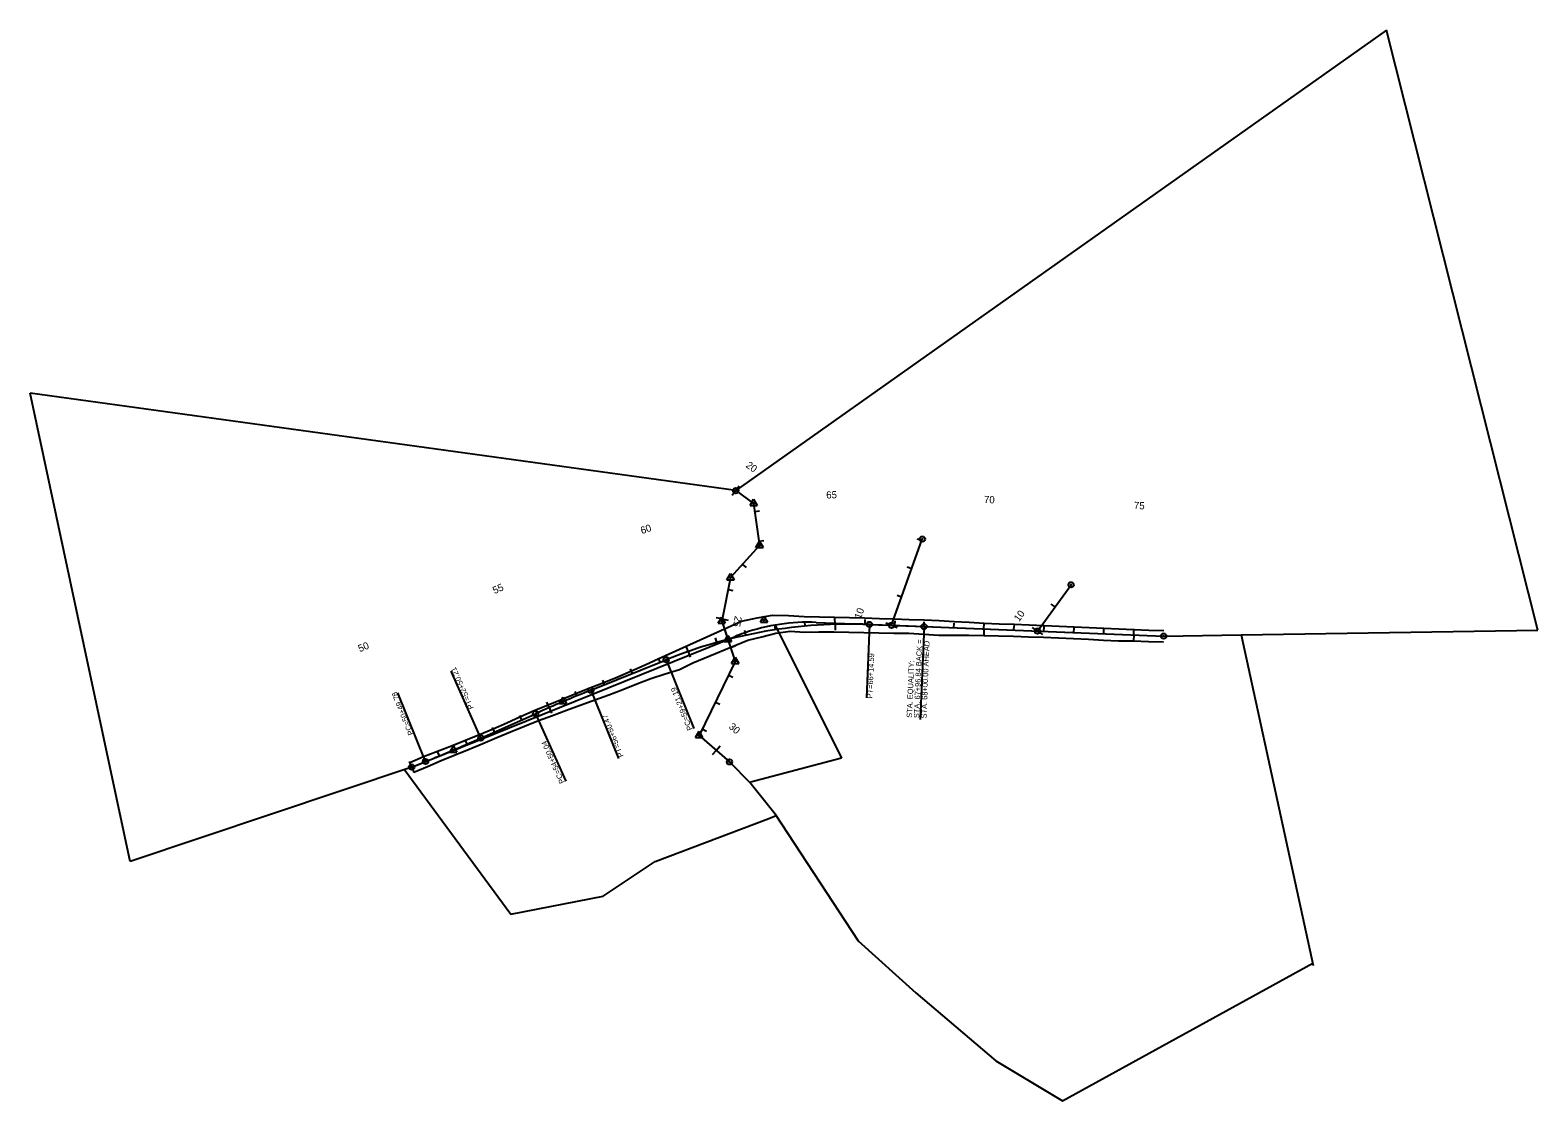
# Model space of a CAD drawing. Extents: x 1965498 to 1970527, y 1116335 to 1119906.
import ezdxf

# ---------------------------------------------------------------- set-up
doc = ezdxf.new("R2010")
doc.units = 0
for name, color, linetype in [('RD_EX_DV_Prop', 7, 'Continuous'), ('RD_EX_RW', 7, 'Continuous'), ('RD_HC_CL', 7, 'Continuous'), ('RD_HC_CL_Rel', 7, 'Continuous'), ('RD_HC_Data', 7, 'Continuous'), ('RD_HC_Data_Rel', 7, 'Continuous'), ('RD_HC_Data_Tic_Rel', 7, 'Continuous'), ('RD_HC_TX_Rel_Sta50', 7, 'Continuous'), ('RD_HC_TX_StaOther', 7, 'Continuous'), ('RD_Sketch2', 7, 'Continuous')]:
    doc.layers.add(name, color=color, linetype=linetype)

msp = doc.modelspace()

# ---------------------------------------------------------------- linework, layer by layer
at = {"layer": 'RD_EX_DV_Prop'}
for p, q in [((1970021.7, 1119906.4), (1967851.7, 1118370.2)), ((1970527.1, 1117904.7), (1970021.7, 1119906.4)), ((1965831.2, 1117132.9), (1965498.1, 1118695)), ((1967851.7, 1118370.2), (1965498.1, 1118695)), ((1967851.7, 1118370.2), (1967911.4, 1118327.7)), ((1967911.4, 1118327.7), (1967931.1, 1118187.5)), ((1967931.1, 1118187.5), (1967834, 1118080)), ((1967834, 1118080), (1967804.8, 1117934.9)), ((1967804.8, 1117934.9), (1967825.2, 1117874.1)), ((1967983.3, 1117921.8), (1968204.3, 1117478.1)), ((1968120.3, 1117930.9), (1968371.4, 1117921)), ((1968371.4, 1117921), (1969279, 1117884.9)), ((1969279, 1117884.9), (1969537.8, 1117889)), ((1969537.8, 1117889), (1970527.1, 1117904.7)), ((1969537.8, 1117889), (1969777.4, 1116786.4)), ((1967698.1, 1117822.7), (1967825.2, 1117874.1)), ((1967825.2, 1117874.1), (1967849.5, 1117883.9)), ((1967825.2, 1117874.1), (1967849.8, 1117800.6)), ((1966770.7, 1117448.1), (1967698.1, 1117822.7)), ((1967849.8, 1117800.6), (1967729.3, 1117553.7)), ((1967729.3, 1117553.7), (1967830.8, 1117465.4)), ((1966770.7, 1117448.1), (1965831.2, 1117132.9)), ((1966745.7, 1117440.8), (1967101.3, 1116957.5)), ((1967830.8, 1117465.4), (1967898.1, 1117396.8)), ((1968204.3, 1117478.1), (1967897.6, 1117396.5)), ((1967983, 1117291.4), (1967898.1, 1117396.8)), ((1967962.1, 1117277.1), (1967986.9, 1117286.5)), ((1967983, 1117291.4), (1968260.1, 1116868.2)), ((1967986.9, 1117286.5), (1967983, 1117291.4)), ((1967582.6, 1117133.3), (1967962.1, 1117277.1)), ((1967409.3, 1117017.8), (1967582.6, 1117133.3)), ((1967101.3, 1116957.5), (1967409.3, 1117017.8)), ((1968260.1, 1116868.2), (1968452.8, 1116695.3)), ((1968941.8, 1116334.8), (1969776.6, 1116794.1)), ((1968452.8, 1116695.3), (1968719.5, 1116468.1)), ((1968719.5, 1116468.1), (1968941.8, 1116334.8))]:
    msp.add_line(p, q, dxfattribs=at)
for start, end in [(109.2117, 111.9958), (87.7266, 109.2117)]:
    msp.add_arc((1968094.4, 1117277.5), 653.9, start, end, dxfattribs=at)
at = {"layer": 'RD_EX_RW'}
for points in [[(1967870.6, 1117935.4), (1967922.7, 1117945.6), (1967974.5, 1117955.3), (1968027.5, 1117953.6), (1968079.5, 1117951), (1968130.7, 1117949), (1968180.7, 1117948.4), (1968230.7, 1117947.1), (1968280.6, 1117945.5), (1968330.6, 1117944), (1968380.6, 1117942.5), (1968430.6, 1117940.9), (1968480.5, 1117939.1), (1968530.5, 1117937.2), (1968580.4, 1117934.2), (1968630.3, 1117931.2), (1968680.3, 1117928.2), (1968730.2, 1117926.4), (1968780.2, 1117924.7), (1968830.1, 1117922.4), (1968880.1, 1117920.9), (1968930, 1117917.9), (1968980, 1117915.8), (1969030, 1117913.7), (1969079.9, 1117911.5), (1969129.9, 1117909.2), (1969179.8, 1117906.8), (1969229.8, 1117904.9), (1969279.7, 1117903.2)], [(1966764.8, 1117463.1), (1966810.5, 1117483.1), (1966857.3, 1117500.8), (1966903.7, 1117519.3), (1966950.1, 1117538.2), (1966996.4, 1117557), (1967042.7, 1117575.8), (1967088.6, 1117595.7), (1967134, 1117616.8), (1967179.6, 1117637.3), (1967226.1, 1117655.7), (1967272.5, 1117674.3), (1967318.5, 1117694.1), (1967365.1, 1117712.2), (1967411.6, 1117730.5), (1967458.2, 1117748.8), (1967504.1, 1117768.7), (1967549.8, 1117788.8), (1967595.2, 1117810), (1967686.2, 1117851.8), (1967870.6, 1117935.4)], [(1967663.6, 1117774.2), (1967708.8, 1117795.8), (1967892.1, 1117872), (1967938.9, 1117882.9), (1967985.3, 1117894.6), (1968032.7, 1117901.4), (1968080.7, 1117898.1), (1968128.7, 1117899.3), (1968178.7, 1117899.4), (1968228.7, 1117898.2), (1968278.7, 1117896.8), (1968328.7, 1117895.5), (1968378.7, 1117895.2), (1968428.7, 1117894.5), (1968478.6, 1117891.5), (1968528.6, 1117888.4), (1968578.6, 1117888), (1968628.6, 1117887.7), (1968678.6, 1117887.4), (1968728.6, 1117886.1), (1968778.6, 1117884.7), (1968828.6, 1117882.9), (1968878.6, 1117881.2), (1968928.5, 1117879.4), (1968978.5, 1117877.6), (1969028.4, 1117874.5), (1969078.3, 1117871.2), (1969128.3, 1117869.8), (1969178.3, 1117868.8), (1969228.3, 1117867.4), (1969278.3, 1117865.8), (1969278.7, 1117865.8)], [(1966777.6, 1117431), (1966823.7, 1117450.6), (1966869.6, 1117470.3), (1966915.9, 1117489.2), (1966962.2, 1117508), (1967008.4, 1117527.3), (1967054.2, 1117547.3), (1967100.7, 1117565.7), (1967146.8, 1117585), (1967193.3, 1117603.6), (1967240.4, 1117620.4), (1967287.4, 1117637.6), (1967381.3, 1117672.1), (1967428.1, 1117689.7), (1967474.9, 1117707.3), (1967521.5, 1117725.4), (1967568.1, 1117743.6), (1967615.7, 1117759.4), (1967663.6, 1117774.2)]]:
    msp.add_lwpolyline(points, dxfattribs=at)
at = {"layer": 'RD_HC_CL'}
for p, q in [((1967851.7, 1118370.2), (1967911.4, 1118327.7)), ((1967911.4, 1118327.7), (1967931.1, 1118187.5)), ((1968371.4, 1117921), (1968474, 1118208.6)), ((1967931.1, 1118187.5), (1967834, 1118080)), ((1967834, 1118080), (1967804.8, 1117934.9)), ((1968858.2, 1117901.7), (1968970.1, 1118056.2)), ((1967804.8, 1117934.9), (1967849.8, 1117800.6)), ((1967849.8, 1117800.6), (1967729.3, 1117553.7)), ((1967729.3, 1117553.7), (1967830.8, 1117465.4))]:
    msp.add_line(p, q, dxfattribs=at)
at = {"layer": 'RD_HC_CL_Rel'}
for p, q in [((1968297.5, 1117923.9), (1968479.6, 1117916.7)), ((1968479.6, 1117916.7), (1969279, 1117884.9)), ((1967368.4, 1117704.6), (1967619.4, 1117806)), ((1967001.4, 1117545.1), (1967183.9, 1117626.3)), ((1966770.7, 1117448.1), (1966816.9, 1117466.8))]:
    msp.add_line(p, q, dxfattribs=at)
for centre, radius, start, end in [((1968232.6, 1116288.2), 1637, 87.7266, 111.9958), ((1969514.4, 1112392.1), 5729.6, 111.99584, 114.00015), ((1964670.9, 1122779.3), 5729.6, 291.9959, 294.00015)]:
    msp.add_arc(centre, radius, start, end, dxfattribs=at)
at = {"layer": 'RD_HC_Data'}
for p, q in [((1967851.7, 1118370.2), (1967840.1, 1118354)), ((1967851.7, 1118370.2), (1967863.4, 1118386.5)), ((1967899.5, 1118320.8), (1967911.4, 1118341.4)), ((1967911.4, 1118341.4), (1967923.3, 1118320.8)), ((1967899.5, 1118320.8), (1967923.3, 1118320.8)), ((1967915.1, 1118301.2), (1967930.9, 1118303.4)), ((1967919.1, 1118180.7), (1967931.1, 1118201.3)), ((1967929, 1118202.2), (1967944.8, 1118204.4)), ((1967931.1, 1118201.3), (1967943, 1118180.7)), ((1968472.1, 1118203.5), (1968457.1, 1118208.9)), ((1967919.1, 1118180.7), (1967943, 1118180.7)), ((1967822.1, 1118073.1), (1967834, 1118093.7)), ((1967834, 1118093.7), (1967845.9, 1118073.1)), ((1967874, 1118124.2), (1967885.9, 1118113.5)), ((1968438.5, 1118109.4), (1968423.5, 1118114.7)), ((1967822.1, 1118073.1), (1967845.9, 1118073.1)), ((1967826.1, 1118040.4), (1967841.7, 1118037.2)), ((1968404.9, 1118015.2), (1968389.9, 1118020.5)), ((1968916.8, 1117982.6), (1968903.9, 1117992)), ((1967806.3, 1117942.4), (1967786.7, 1117946.3)), ((1967792.9, 1117928), (1967804.8, 1117948.6)), ((1967804.8, 1117948.6), (1967816.7, 1117928)), ((1967806.3, 1117942.4), (1967825.9, 1117938.4)), ((1967792.9, 1117928), (1967816.7, 1117928)), ((1967813.4, 1117866.9), (1967825.3, 1117887.5)), ((1967825.3, 1117887.5), (1967837.2, 1117866.9)), ((1968371.4, 1117921), (1968352.5, 1117927.7)), ((1968371.4, 1117921), (1968390.2, 1117914.3)), ((1968858.2, 1117901.7), (1968842, 1117913.4)), ((1968858.2, 1117901.7), (1968874.4, 1117889.9)), ((1967813.4, 1117866.9), (1967837.2, 1117866.9)), ((1967834.2, 1117847.3), (1967849.3, 1117852.4)), ((1967837.9, 1117793.7), (1967849.8, 1117814.4)), ((1967837.9, 1117793.7), (1967861.7, 1117793.7)), ((1967849.8, 1117814.4), (1967861.7, 1117793.7)), ((1967827.6, 1117755), (1967841.9, 1117748)), ((1967783.7, 1117665.1), (1967798.1, 1117658.1)), ((1967717.4, 1117546.8), (1967729.3, 1117567.4)), ((1967717.4, 1117546.8), (1967741.2, 1117546.8)), ((1967729.3, 1117567.4), (1967741.2, 1117546.8)), ((1967739.8, 1117575.2), (1967754.2, 1117568.2)), ((1967786.6, 1117503.8), (1967773.5, 1117488.7)), ((1967786.6, 1117503.8), (1967799.8, 1117518.9))]:
    msp.add_line(p, q, dxfattribs=at)
for centre, radius in [((1967851.7, 1118370.2), 9), ((1967851.7, 1118370.2), 0.845), ((1967911.4, 1118327.7), 1.59), ((1967931.1, 1118187.5), 1.59), ((1968474, 1118208.6), 9), ((1968474, 1118208.6), 0.845), ((1967834, 1118080), 1.59), ((1968970.1, 1118056.2), 9), ((1968970.1, 1118056.2), 0.845), ((1967804.8, 1117934.9), 1.59), ((1968371.4, 1117921), 9), ((1968371.4, 1117921), 0.845), ((1968858.2, 1117901.7), 9), ((1968858.2, 1117901.7), 0.845), ((1967825.3, 1117873.7), 1.59), ((1967849.8, 1117800.6), 1.59), ((1967729.3, 1117553.7), 1.59), ((1967830.8, 1117465.4), 9), ((1967830.8, 1117465.4), 0.845)]:
    msp.add_circle(centre, radius, dxfattribs=at)
at = {"layer": 'RD_HC_Data_Rel'}
for p, q in [((1967933.9, 1117931), (1967945.8, 1117951.6)), ((1967945.8, 1117951.6), (1967957.7, 1117931)), ((1967933.9, 1117931), (1967957.7, 1117931)), ((1968297.5, 1117923.9), (1968287.8, 1117678.6)), ((1968479.6, 1117916.7), (1968467.3, 1117606.4)), ((1967619.4, 1117806), (1967712, 1117577)), ((1967001.4, 1117545.1), (1966902.3, 1117767.7)), ((1966816.9, 1117466.8), (1966724.5, 1117695.5)), ((1967368.4, 1117704.6), (1967460.4, 1117477)), ((1967263.6, 1117660.2), (1967275.5, 1117680.9)), ((1967263.6, 1117660.2), (1967287.4, 1117660.2)), ((1967275.5, 1117680.9), (1967287.4, 1117660.2)), ((1967183.9, 1117626.3), (1967284.4, 1117400.7)), ((1966897.9, 1117497.4), (1966909.8, 1117518.1)), ((1966897.9, 1117497.4), (1966921.7, 1117497.4)), ((1966909.8, 1117518.1), (1966921.7, 1117497.4))]:
    msp.add_line(p, q, dxfattribs=at)
for centre, radius in [((1967945.8, 1117937.9), 1.59), ((1968297.5, 1117923.9), 9), ((1968297.5, 1117923.9), 0.845), ((1968479.6, 1117916.7), 9), ((1968479.6, 1117916.7), 0.845), ((1969279, 1117884.9), 9), ((1969279, 1117884.9), 0.845), ((1967619.4, 1117806), 9), ((1967619.4, 1117806), 0.845), ((1967368.4, 1117704.6), 9), ((1967368.4, 1117704.6), 0.845), ((1967183.9, 1117626.3), 9), ((1967275.5, 1117667.1), 1.59), ((1967183.9, 1117626.3), 0.845), ((1967001.4, 1117545.1), 9), ((1967001.4, 1117545.1), 0.845), ((1966909.8, 1117504.3), 1.59), ((1966770.7, 1117448.1), 9), ((1966770.7, 1117448.1), 0.845), ((1966816.9, 1117466.8), 9), ((1966816.9, 1117466.8), 0.845)]:
    msp.add_circle(centre, radius, dxfattribs=at)
at = {"layer": 'RD_HC_Data_Tic_Rel'}
for p, q in [((1968182.9, 1117924.4), (1968182.3, 1117944.4)), ((1968282.9, 1117924.4), (1968283.4, 1117940.4)), ((1967885.6, 1117888), (1967882.2, 1117903.6)), ((1967983.9, 1117906.2), (1967981.5, 1117922)), ((1968083.1, 1117918.4), (1968081.7, 1117934.3)), ((1968182.9, 1117924.4), (1968183.5, 1117904.5)), ((1968382.8, 1117920.5), (1968383.5, 1117936.5)), ((1968479.6, 1117916.7), (1968480.3, 1117932.7)), ((1968579.6, 1117912.7), (1968580.2, 1117928.7)), ((1968679.5, 1117908.7), (1968678.7, 1117888.8)), ((1968679.5, 1117908.7), (1968680.3, 1117928.7)), ((1968779.4, 1117904.8), (1968780, 1117920.8)), ((1968879.3, 1117900.8), (1968880, 1117916.8)), ((1968979.3, 1117896.8), (1968979.9, 1117912.8)), ((1969079.2, 1117892.9), (1969079.8, 1117908.9)), ((1969179.1, 1117888.9), (1969178.3, 1117868.9)), ((1969179.1, 1117888.9), (1969179.9, 1117908.9)), ((1967693.2, 1117833.8), (1967686.6, 1117852.7)), ((1967788.6, 1117863.8), (1967784.2, 1117879.2)), ((1967599.8, 1117798.1), (1967593.8, 1117812.9)), ((1967693.2, 1117833.8), (1967699.8, 1117814.9)), ((1967414.4, 1117723.2), (1967408.4, 1117738)), ((1967507.1, 1117760.7), (1967501.1, 1117775.5)), ((1967321.7, 1117685.5), (1967315.6, 1117700.3)), ((1967229.7, 1117646.5), (1967221.7, 1117664.8)), ((1967229.7, 1117646.5), (1967237.6, 1117628.1)), ((1967138.2, 1117606), (1967131.7, 1117620.6)), ((1966955.4, 1117524.8), (1966949, 1117539.5)), ((1967046.9, 1117565.3), (1967040.4, 1117579.9)), ((1966863.4, 1117485.8), (1966857.3, 1117500.6)), ((1966770.7, 1117448.1), (1966763.2, 1117466.7)), ((1966770.7, 1117448.1), (1966778.2, 1117429.6))]:
    msp.add_line(p, q, dxfattribs=at)
at = {"layer": 'RD_Sketch2'}
msp.add_line((1967183.9, 1117626.3), (1967183.9, 1117626.3), dxfattribs=at)

# ---------------------------------------------------------------- texts
at = {"layer": 'RD_HC_Data_Rel'}
for s, rotation, p in [('STA. 67+96.84 BACK =', 87.7266, (1968463.6, 1117611.2)), ('STA. 68+00.00 AHEAD', 87.7266, (1968487.9, 1117610.2)), ('PT=66+14.59', 87.7266, (1968307.6, 1117676.9)), ('STA. EQUALITY:', 87.7266, (1968439.4, 1117612.1)), ('PT=52+50.21', 114.0002, (1966978.2, 1117645.7)), ('PC=50+49.78', 111.9959, (1966777.6, 1117558.7)), ('PC=59+21.19', 111.9958, (1967708.3, 1117574.4)), ('PT=56+50.47', 111.9958, (1967478.2, 1117485.1)), ('PC=54+50.04', 114.0002, (1967281.8, 1117397.7))]:
    msp.add_text(s, height=18, rotation=rotation, dxfattribs=at).set_placement(p)
at = {"layer": 'RD_HC_TX_Rel_Sta50'}
for s, rotation, p in [('65', 1.7374, (1968153.8, 1118343.8)), ('70', 357.7266, (1968679.3, 1118329.1)), ('75', 357.7266, (1969179.4, 1118309.2)), ('60', 19.2374, (1967538.9, 1118224.8)), ('55', 23.5006, (1967047.1, 1118025.1)), ('50', 21.9959, (1966597.8, 1117831.2))]:
    msp.add_text(s, height=24, rotation=rotation, dxfattribs=at).set_placement(p)
at = {"layer": 'RD_HC_TX_StaOther'}
for s, rotation, p in [('20', 324.4755, (1967883.2, 1118450.2)), ('25', 258.6104, (1967849.1, 1117953.4)), ('10', 70.3698, (1968268.9, 1117940.3)), ('10', 54.0772, (1968796.5, 1117931.2)), ('30', 318.9993, (1967826.3, 1117579.7))]:
    msp.add_text(s, height=24, rotation=rotation, dxfattribs=at).set_placement(p)

doc.saveas('drawing.dxf')
